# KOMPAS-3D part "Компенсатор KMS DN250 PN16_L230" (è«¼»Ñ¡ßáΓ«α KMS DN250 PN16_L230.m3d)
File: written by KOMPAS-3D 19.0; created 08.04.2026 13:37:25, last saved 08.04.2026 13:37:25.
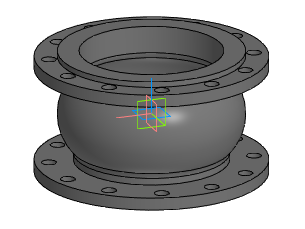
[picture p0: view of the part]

Document properties: Автор: Энергия; Полное имя файла: Z:\3.Личные\kachalov\3d для проектировщиков\7.1 Компенсатор\stp_Компенсатор KSM\Компенсатор KMS DN250 PN16_L230.m3d

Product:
- Part/product: Компенсатор KMS DN250 PN16_L230

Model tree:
1. Операция без истории:1  (labels: Компенсатор KMS DN250 PN16_L230)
